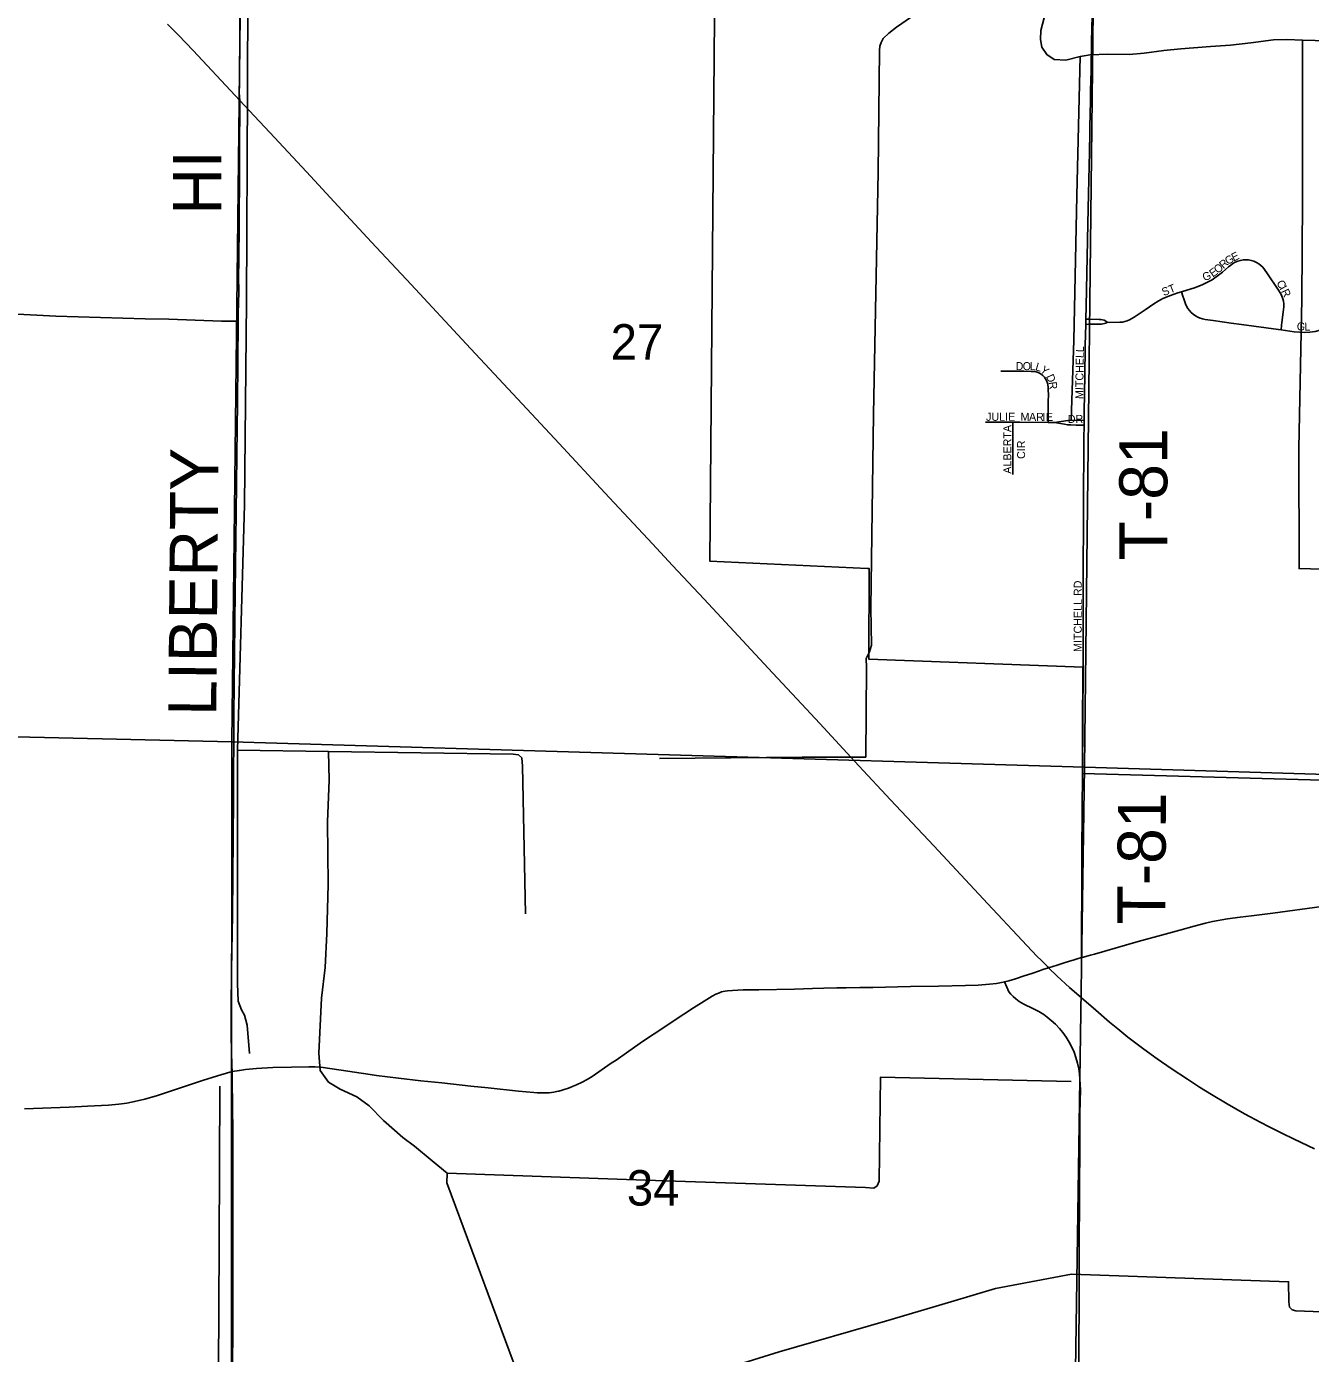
# Model space of a CAD drawing. Extents: x 1443599 to 1910620, y 1028088 to 1361369.
# Drawn here: x 1635252 to 1643273, y 1221564 to 1229853 of the extents above; entities that cross this region are included whole.
import ezdxf

# ---------------------------------------------------------------- set-up
doc = ezdxf.new("R2010")
doc.units = 0
for name, color, linetype in [('GM_X_City_Street', 7, 'Continuous'), ('GM_X_City_Street_Text', 7, 'Continuous'), ('GM_X_Corporation', 7, 'Continuous'), ('GM_X_County_Road', 7, 'Continuous'), ('GM_X_County_Road_Text', 7, 'Continuous'), ('GM_X_Minor_River', 7, 'Continuous'), ('GM_X_Section', 7, 'Continuous'), ('GM_X_Section_Text', 7, 'Continuous'), ('GM_X_Township_Road', 7, 'Continuous'), ('GM_X_Township_Road_Text', 7, 'Continuous'), ('GM_X_US_Route', 7, 'Continuous')]:
    doc.layers.add(name, color=color, linetype=linetype)

msp = doc.modelspace()

# ---------------------------------------------------------------- linework, layer by layer
at = {"layer": 'GM_X_City_Street'}
for points in [[(1641870.1, 1228025.2), (1641871.8, 1228106.3), (1641882.7, 1228621.4), (1641886.8, 1228808.4), (1641892.3, 1229070.9), (1641894.6, 1229188.5), (1641895.4, 1229228.4), (1641898, 1229385.9), (1641899.9, 1229468.9), (1641900.6, 1229500.7), (1641902.1, 1229592.6), (1641905.7, 1229746.8), (1641907.7, 1229848.5), (1641910.9, 1229973.2), (1641913.3, 1230078.2), (1641917.1, 1230219.2), (1641920.4, 1230383.3), (1641923.9, 1230505.5)], [(1642467.3, 1228196.1), (1642554.7, 1228223.6), (1642600.4, 1228241.5), (1642629.8, 1228255.6), (1642658.1, 1228271.8), (1642698.7, 1228299.2), (1642724.4, 1228319.5), (1642761.7, 1228351.9), (1642774.8, 1228362.4), (1642788.7, 1228372), (1642803.3, 1228380.5), (1642819, 1228387.2), (1642835.4, 1228392), (1642852.2, 1228395), (1642869.2, 1228395.9), (1642886.2, 1228395), (1642903.1, 1228392), (1642919.4, 1228387), (1642935, 1228380), (1642949.6, 1228371.3), (1642963.1, 1228360.9), (1642975.3, 1228349.1), (1642986.2, 1228336.2), (1643005.5, 1228308.9), (1643070.1, 1228213.1), (1643087.2, 1228184.4), (1643094.5, 1228169.1), (1643100.4, 1228153.2), (1643104.4, 1228136.7), (1643106.6, 1228120), (1643106.7, 1228103), (1643103.1, 1228069.6), (1643094.1, 1228004.4), (1643092.5, 1227988.1), (1643089.6, 1227958.7)], [(1642002.8, 1228005.9), (1642015.9, 1228005.4), (1642081.9, 1228006), (1642098, 1228007.1), (1642113.4, 1228009.9), (1642128.5, 1228014.7), (1642143.2, 1228021.2), (1642171.4, 1228037.2), (1642239.5, 1228083.3), (1642293.6, 1228121.3), (1642322, 1228138.6), (1642351.7, 1228153.7), (1642397.7, 1228172.8), (1642444.7, 1228188.9), (1642467.3, 1228196.1)], [(1642467.3, 1228196.1), (1642476.1, 1228168), (1642481, 1228152.2), (1642492.3, 1228121.2), (1642499.5, 1228106.4), (1642507.9, 1228092.3), (1642517.7, 1228079), (1642528.7, 1228066.7), (1642540.9, 1228055.7), (1642554.3, 1228046.1), (1642568.6, 1228038), (1642583.8, 1228031.6), (1642599.5, 1228026.6), (1642615.5, 1228022.9), (1642664.5, 1228016.1), (1642778.4, 1227999.3), (1642841.7, 1227991), (1643073, 1227961), (1643089.6, 1227958.7)], [(1643089.6, 1227958.7), (1643170.9, 1227947.1), (1643203.6, 1227943.4), (1643236.5, 1227942.6), (1643269.4, 1227944.6), (1643302.1, 1227949.1), (1643334.4, 1227955.7), (1643366.1, 1227964.8), (1643396.6, 1227977.1), (1643426.1, 1227991.8), (1643527.6, 1228046.9), (1643571.8, 1228068.9), (1643602.6, 1228080.8), (1643618.3, 1228085.5), (1643634.4, 1228089.2), (1643667.1, 1228093.9), (1643700, 1228095.6), (1643716.4, 1228095.1), (1643732.8, 1228093.3), (1643749.1, 1228090.6), (1643781, 1228082.3), (1643811.6, 1228070.1), (1643990, 1227984.7), (1644023.5, 1227968.6)], [(1641859.5, 1227392.6), (1641860.3, 1227460.5), (1641861.8, 1227546), (1641866.1, 1227831), (1641866.6, 1227863.5), (1641869.4, 1227992.8)], [(1641869.4, 1227992.8), (1641870.1, 1228025.2)], [(1641869.4, 1227992.8), (1641886.4, 1227993), (1641953.6, 1227993.3), (1641966.9, 1227994.5), (1641976.2, 1227996.1), (1641985.6, 1227997.3), (1641994.2, 1228000), (1642002.8, 1228005.9)], [(1641870.1, 1228025.2), (1641886.8, 1228025), (1641953.2, 1228023.8), (1641962.9, 1228023.2), (1641973.5, 1228021.5), (1641983.8, 1228018.5), (1641995, 1228012.9), (1642002.8, 1228005.9)], [(1641635.1, 1227380.4), (1641635.1, 1227408.7), (1641634.9, 1227510.8), (1641635.7, 1227553.5), (1641634.9, 1227583.1), (1641634.1, 1227601.4), (1641632, 1227615.8), (1641630, 1227625.5), (1641624.7, 1227641.1), (1641618.7, 1227652.9), (1641611.2, 1227663.6), (1641602, 1227673.1), (1641591.7, 1227681.2), (1641580.3, 1227687.9), (1641571.7, 1227692.2), (1641560.4, 1227695.7), (1641551.4, 1227697.3), (1641541.6, 1227698.4), (1641529.3, 1227699.1), (1641483.2, 1227699.8), (1641338.3, 1227699.6)], [(1641242.3, 1227382.8), (1641413.9, 1227381.7)], [(1641414.4, 1227054.8), (1641414.2, 1227173.6), (1641414.1, 1227264.7), (1641413.9, 1227354.9), (1641413.9, 1227381.7)], [(1641413.9, 1227381.7), (1641456.8, 1227381.5), (1641635.1, 1227380.4)], [(1641635.1, 1227380.4), (1641641.6, 1227380.3), (1641674.3, 1227379.8)], [(1641674.3, 1227379.8), (1641756.6, 1227392), (1641769.4, 1227393.1), (1641778, 1227393.4), (1641855.9, 1227392.6), (1641859.5, 1227392.6)], [(1641674.3, 1227379.8), (1641735.6, 1227369.4), (1641755.2, 1227366.2), (1641766.8, 1227364.8), (1641775.9, 1227364.3), (1641808.4, 1227363.4), (1641855.3, 1227363.2), (1641859.1, 1227363.2)], [(1641858, 1227275.4), (1641858.1, 1227279.6), (1641859.1, 1227363.2)], [(1641859.1, 1227363.2), (1641859.5, 1227392.6)], [(1641852.1, 1225851), (1641852.9, 1226241.7), (1641854.1, 1226486.9), (1641854, 1226512)]]:
    msp.add_lwpolyline(points, dxfattribs=at)
at = {"layer": 'GM_X_Corporation'}
msp.add_lwpolyline([(1644469.3, 1225113.5), (1641849.1, 1225187.9), (1641852.1, 1225851), (1640515.2, 1225901.2), (1640516.8, 1226466.9), (1640506.5, 1226467.4), (1639520.2, 1226514.5), (1639554.2, 1230393.3), (1639823.2, 1230383.9), (1639829.8, 1230585.9), (1640492.7, 1230559.9), (1640517.7, 1231451.5), (1639625.7, 1231464.8), (1639684.8, 1233228.6), (1640615.3, 1233192.7), (1640709.4, 1235840.8), (1642046.8, 1235796.5), (1642085.4, 1238455.5), (1644168.5, 1238399.6)], dxfattribs=at)
at = {"layer": 'GM_X_County_Road'}
for points in [[(1636583.8, 1229392.1), (1636581.2, 1229440.2), (1636582.7, 1229522), (1636584.2, 1229817.4), (1636585.1, 1230063.5), (1636586.9, 1230440.7), (1636586.5, 1230643.4)], [(1636574.6, 1228013.4), (1636575.1, 1228062.3), (1636578.6, 1228193.5), (1636577.3, 1228292), (1636578.4, 1228390.3), (1636579.8, 1228620), (1636581.6, 1228948.1), (1636582.8, 1229161.3), (1636584.9, 1229292.5), (1636585.6, 1229358.4), (1636583.8, 1229392.1)], [(1636536.5, 1223324.9), (1636535.4, 1223360.8), (1636532.7, 1223453), (1636531.2, 1223551.3), (1636530.8, 1223715.3), (1636532.7, 1223961.3), (1636538.1, 1224305.8), (1636542.6, 1224781.5), (1636544.3, 1225027.6), (1636547.1, 1225552.5), (1636555, 1226323.5), (1636561, 1226815.6), (1636566, 1227176.5), (1636570.1, 1227504.6), (1636574.6, 1228013.4)], [(1641841.9, 1224036.9), (1641847.7, 1224038.6), (1641898.1, 1224052.8), (1641923.4, 1224059.6), (1642117.6, 1224114.9), (1642196.4, 1224137.1), (1642364.8, 1224183.7), (1642457.4, 1224209.3), (1642547.3, 1224234.1), (1642617, 1224252.3), (1642662.1, 1224261.8), (1642755.2, 1224278.6), (1642833, 1224289.8), (1642904.6, 1224298.7), (1643038.2, 1224315.3), (1643343.9, 1224355.8)], [(1641636.7, 1223973.5), (1641691.4, 1223990.2), (1641741.6, 1224005.7), (1641781.7, 1224018.7)], [(1641781.7, 1224018.7), (1641791.4, 1224021.8), (1641816.3, 1224029.5), (1641841.9, 1224036.9)], [(1641361.6, 1223886.3), (1641388.8, 1223893), (1641429.8, 1223905.2), (1641484.6, 1223922.8)], [(1641484.6, 1223922.8), (1641533.1, 1223938.3), (1641580.8, 1223955.4)], [(1641580.8, 1223955.4), (1641601, 1223962.6), (1641636.7, 1223973.5)], [(1636536.5, 1223324.9), (1636582, 1223332.5), (1636619.6, 1223338.2), (1636688.9, 1223344.1), (1636791.6, 1223349.8), (1636908, 1223353.7), (1637016.1, 1223355.6), (1637055.3, 1223354.8), (1637091, 1223351.9), (1637162.4, 1223343), (1637399.3, 1223306.8), (1637438.3, 1223301.2), (1637575, 1223283.6), (1637715.4, 1223268.2), (1637845.9, 1223254.2), (1638028.7, 1223234.7), (1638136.5, 1223223.6), (1638325.7, 1223202.9), (1638420.5, 1223193.8), (1638442.6, 1223192.2), (1638460.1, 1223191.8), (1638486.6, 1223191.5), (1638516.4, 1223193.1), (1638532.1, 1223194.7), (1638546.1, 1223196.9), (1638563.2, 1223200.1), (1638578.5, 1223203.8), (1638598, 1223208.7), (1638616.8, 1223214.4), (1638632.7, 1223219.6), (1638648.1, 1223225.2), (1638667.9, 1223233.2), (1638687.8, 1223241.6), (1638723.5, 1223258.6), (1638755.5, 1223275.9), (1638786.4, 1223295), (1638905.4, 1223376.9), (1638934.9, 1223397.1), (1638999.4, 1223442), (1639051, 1223477), (1639107.5, 1223516.5), (1639172.7, 1223560.4), (1639359.2, 1223683), (1639418.7, 1223723.3), (1639536.3, 1223796.4), (1639559.3, 1223807.8), (1639580.9, 1223817.5), (1639594.4, 1223822.8), (1639605, 1223825.7), (1639617.5, 1223828.1), (1639630.5, 1223829.5), (1639663.3, 1223831.9), (1639728.7, 1223835), (1639827.7, 1223836.6), (1640049.7, 1223840.6), (1640162.7, 1223843.8), (1640232.3, 1223846), (1640314.1, 1223847.4), (1640373, 1223849.2), (1640458.2, 1223850.7), (1640540.1, 1223851), (1640773.6, 1223855.8), (1640949.7, 1223859), (1641118.7, 1223862.2), (1641196.6, 1223864.4), (1641268.8, 1223870.3), (1641311.3, 1223876.2), (1641352.5, 1223884.1), (1641361.6, 1223886.3)], [(1635239.3, 1223092.3), (1635518.1, 1223103.9), (1635632.8, 1223108.6), (1635764, 1223114.8), (1635829.6, 1223121), (1635878.6, 1223128), (1635927.1, 1223137.3), (1635991.1, 1223153.2), (1636070, 1223176.4), (1636194.9, 1223217.1), (1636350.5, 1223269.6), (1636444.2, 1223299.3), (1636523.1, 1223321.2), (1636536.5, 1223324.9)], [(1636480.1, 1220079.3), (1636494.3, 1220190.4), (1636513.6, 1220320.3), (1636525.4, 1220418.2), (1636532.4, 1220500.1), (1636535.8, 1220582.2), (1636536.5, 1220713.6), (1636536.8, 1220910.5), (1636537.7, 1221041.6), (1636539.1, 1221271.3), (1636538.3, 1221337.1), (1636536.6, 1221402.5), (1636538.5, 1221484.3), (1636540.4, 1221714.1), (1636540.2, 1221894.6), (1636540.9, 1222353.9), (1636540.3, 1222665.6), (1636540.7, 1222846), (1636540, 1222960.9), (1636539.4, 1223092.1), (1636537.6, 1223288.9), (1636536.5, 1223324.9)]]:
    msp.add_lwpolyline(points, dxfattribs=at)
at = {"layer": 'GM_X_Minor_River'}
for points in [[(1636644.4, 1223438), (1636630.9, 1223614.5), (1636613.1, 1223676.8), (1636595.2, 1223710.9), (1636575.3, 1223765.1), (1636569.6, 1223875.5), (1636570, 1225333.8), (1636614.6, 1226866.2), (1636626.5, 1228134), (1636632.4, 1229453.9), (1636634.3, 1230073.7), (1636638.2, 1230697.6), (1636641.5, 1231154.9), (1636640.3, 1231413.7), (1636520.1, 1231420.1), (1635959.2, 1231431.7), (1635494.5, 1231443.1)], [(1639206.2, 1225281.9), (1640097.7, 1225289.3), (1640494.4, 1225290.1), (1640500.1, 1225849.7), (1640498.2, 1225905.9), (1640518.4, 1225948), (1640530.5, 1225988.1), (1640527.2, 1226222.8), (1640542.9, 1227432.3), (1640573.5, 1228942.7), (1640581.8, 1229703), (1640583.8, 1229731), (1640591.9, 1229753.1), (1640604, 1229779.1), (1640638.2, 1229811.1), (1640686.4, 1229849.1), (1640780.7, 1229913), (1640913.1, 1229980.8), (1641019.5, 1230024.6), (1641119.7, 1230052.4), (1641260, 1230090), (1641430.4, 1230109.6), (1641548.6, 1230127.3), (1641642.8, 1230120.9)], [(1641610.1, 1229908.4), (1641587.8, 1229828.2), (1641585.6, 1229772.1), (1641595.5, 1229723.9), (1641625.4, 1229677.7), (1641671.4, 1229647.4), (1641745.5, 1229643.2), (1641833.7, 1229665), (1641897.9, 1229676.8), (1642008.1, 1229680.5), (1642140.3, 1229678.1), (1642234.5, 1229687.8), (1642356.7, 1229703.5), (1642462.9, 1229713.2), (1642649.3, 1229728.6), (1642773.5, 1229736.3), (1642899.7, 1229751.9), (1643042, 1229769.6), (1643126.2, 1229771.3), (1643224.3, 1229769), (1643540.8, 1229760)], [(1643224.3, 1229769), (1643223.3, 1228764), (1643219.5, 1228150.2), (1643200.6, 1227219.5), (1643202.4, 1226467.2), (1643272.5, 1226465), (1643546.9, 1226460.2), (1644175.9, 1226448.2), (1644716.8, 1226432.5), (1645209.6, 1226425)], [(1641833.7, 1229665), (1641813.1, 1228798.5), (1641794.3, 1227891.8), (1641778.8, 1227394.4)], [(1638369.9, 1224311.5), (1638350.6, 1225232.3), (1638346.8, 1225284.5), (1638324.8, 1225304.6), (1638292.8, 1225308.7), (1637138.9, 1225324.1), (1636570, 1225333.8)], [(1641778.4, 1223262.2), (1640586.5, 1223289.9), (1640578.5, 1222640), (1640566.4, 1222611.9), (1640544.4, 1222597.9), (1640494.3, 1222600.1), (1639118.1, 1222646.4), (1637880.2, 1222690.1), (1637786.3, 1222768.6), (1637676.4, 1222859.2), (1637602.4, 1222913.6), (1637482.6, 1223020.3), (1637392.7, 1223110.8), (1637314.7, 1223167.2), (1637210.7, 1223215.7), (1637138.7, 1223260), (1637086.8, 1223332.4), (1637079.1, 1223440.7), (1637094.2, 1223783.7), (1637118.8, 1223976.2), (1637127.5, 1224186.8), (1637136.4, 1224493.7), (1637131.6, 1224884.8), (1637142.4, 1225145.6), (1637138.9, 1225324.1)], [(1636459.5, 1223233.9), (1636456.5, 1222247), (1636449, 1221067.5), (1636447.1, 1220435.6), (1636422.6, 1220307.3), (1636396.1, 1220128.9), (1636363.4, 1219914.4), (1636344.8, 1219741.9), (1636328.2, 1219531.3), (1636301.5, 1219340.8), (1636299.8, 1218109.3)], [(1644484.4, 1221781.5), (1643182.4, 1221831.6), (1643158.4, 1221837.8), (1643142.4, 1221853.8), (1643138.5, 1221885.9), (1643136.9, 1222012.3), (1641780.8, 1222060.6), (1641305.7, 1221969.8), (1641027, 1221886.4), (1640618, 1221765.3), (1639954.3, 1221574.7), (1639132.2, 1221318.4), (1638347, 1221368.9), (1637878, 1222630), (1637880.2, 1222690.1)]]:
    msp.add_lwpolyline(points, dxfattribs=at)
at = {"layer": 'GM_X_Section'}
for points in [[(1631247.2, 1230796.7), (1636595.3, 1230648.8), (1636534.6, 1225385.5), (1631218.1, 1225507)], [(1636595.3, 1230648.8), (1640040.1, 1230599.8), (1641921.5, 1230497.2), (1641860.6, 1225227.8), (1636534.6, 1225385.5)], [(1641921.5, 1230497.2), (1644385, 1230387), (1647258, 1230369.4), (1647094.6, 1225069.2), (1641860.6, 1225227.8)], [(1636534.6, 1225385.5), (1636531.6, 1220105.4), (1636391.5, 1220105.2), (1631224.9, 1220206.8), (1631218.1, 1225507)], [(1641860.6, 1225227.8), (1641781.3, 1219928.7), (1636531.6, 1220105.4), (1636534.6, 1225385.5)], [(1641860.6, 1225227.8), (1647094.6, 1225069.2), (1647137.2, 1219766.5), (1641781.3, 1219928.7)]]:
    msp.add_lwpolyline(points, close=True, dxfattribs=at)
at = {"layer": 'GM_X_Township_Road'}
for points in [[(1635156.9, 1228058.4), (1635435.7, 1228044.6), (1635714.8, 1228036.6), (1635993.8, 1228027.8), (1636141.5, 1228024.7), (1636469.8, 1228013.6), (1636535.5, 1228012.8), (1636551.9, 1228013), (1636574.6, 1228013.4)], [(1641854, 1226512), (1641854, 1226512.6), (1641854, 1226512.6), (1641854.7, 1226709.4), (1641854.9, 1226837.1), (1641855, 1226964.9), (1641856.7, 1227170.4), (1641857, 1227213.9), (1641858, 1227275.4)], [(1641849.1, 1225187.9), (1641849.1, 1225189), (1641849.2, 1225303.8), (1641849.3, 1225353.2), (1641849.4, 1225486.2), (1641849.5, 1225559.9), (1641849.8, 1225585), (1641850.9, 1225714.6), (1641851.1, 1225740.2), (1641852, 1225847.9), (1641852.1, 1225851)], [(1641841.9, 1224036.9), (1641842, 1224063.5), (1641842.5, 1224237.3), (1641844.1, 1224421), (1641844.5, 1224575.2), (1641844.5, 1224686.8), (1641847.4, 1224962.3), (1641849.1, 1225187.9)], [(1641834.4, 1223142.1), (1641835.6, 1223210.4), (1641833.1, 1223277.9), (1641830.3, 1223310.6), (1641825.6, 1223343.1), (1641818.1, 1223378.4), (1641808.1, 1223413.1), (1641796, 1223447.1), (1641782.9, 1223477.2), (1641766.5, 1223509.4), (1641747.6, 1223540.2), (1641726.2, 1223569.3), (1641705.2, 1223594.5), (1641680.4, 1223620.8), (1641653.8, 1223645.2), (1641628.2, 1223665.7), (1641606.8, 1223680.9), (1641576.1, 1223699.8), (1641538.3, 1223719.6), (1641482.2, 1223747.1), (1641453.8, 1223763.7), (1641432.4, 1223778.9), (1641415, 1223793.8), (1641401.5, 1223808.1), (1641389.7, 1223823.9), (1641381.6, 1223838.1), (1641375.3, 1223853.3), (1641361.6, 1223886.3)], [(1641807.1, 1219917.5), (1641810.3, 1219961), (1641813.5, 1220034.7), (1641817.5, 1220116.7), (1641819.2, 1220198.7), (1641819.7, 1220447.2), (1641820.4, 1220838.9), (1641822.2, 1221157.3), (1641823.8, 1221354.3), (1641827.7, 1221876.2), (1641828.7, 1222152), (1641828.9, 1222289.8), (1641829.9, 1222483.5), (1641830.8, 1222648.1), (1641831.6, 1222798.5), (1641833, 1223061.3), (1641834.4, 1223142.1)]]:
    msp.add_lwpolyline(points, dxfattribs=at)
at = {"layer": 'GM_X_US_Route'}
for points in [[(1636132.8, 1229868.8), (1636202.3, 1229798.9), (1636292.7, 1229703.5), (1636583.8, 1229392.1), (1636642.4, 1229329.4), (1636773, 1229191.7), (1637001.2, 1228944.7), (1637198.4, 1228731.9), (1637406.7, 1228507.2), (1637655.3, 1228240.8), (1637999.3, 1227870.5), (1638348.5, 1227495.9), (1638579, 1227248.6), (1638865.6, 1226941.3), (1639162.7, 1226621.4), (1639287.5, 1226486.5), (1639484.9, 1226275.7), (1639885, 1225845.4), (1640093.7, 1225622.6), (1640208.2, 1225500.4), (1640452.4, 1225234.4), (1640649.8, 1225023.6), (1640919.4, 1224736.3), (1641256.6, 1224373.2), (1641472.1, 1224143.3), (1641564.7, 1224045.7), (1641591.9, 1224018.4)], [(1641591.9, 1224018.4), (1641629.4, 1223980.6), (1641636.7, 1223973.5), (1641690.9, 1223921.6), (1641768.6, 1223851.2), (1641932.2, 1223707.8), (1642018.6, 1223633.7), (1642070, 1223591.4), (1642133.1, 1223540.6), (1642232.2, 1223465.1), (1642314.5, 1223405.4), (1642403.5, 1223343.8), (1642504.8, 1223277), (1642580.3, 1223228), (1642654.7, 1223182.7), (1642753.1, 1223123.6), (1642861.4, 1223061.9), (1642962.4, 1223007.4), (1643011.2, 1222982.3), (1643093.7, 1222941.1), (1643170.5, 1222902.9), (1643298.2, 1222843)]]:
    msp.add_lwpolyline(points, dxfattribs=at)

# ---------------------------------------------------------------- texts
at = {"layer": 'GM_X_City_Street_Text'}
for s, rotation, p in [('R', 42.33312, (1642730.1, 1228337.1)), ('G', 32.09573, (1642757.5, 1228362.3)), ('E', 26.05186, (1642793.6, 1228385)), ('G', 21.15205, (1642609.7, 1228261.8)), ('E', 36.62168, (1642663.6, 1228284.7)), ('O', 39.29584, (1642693.9, 1228307.3)), ('ST', 21.80392, (1642356.2, 1228168.5)), ('C', 299.2056, (1643058.6, 1228252.5)), ('I', 299.24432, (1643077.9, 1228217.9)), ('R', 295.56569, (1643088.3, 1228199.5)), ('G', 355.0331, (1643185.7, 1227957.5)), ('L', 1.23779, (1643235.5, 1227953.6)), ('MITCHELL', 89.19436, (1641853.1, 1227525.9)), ('D', 359.75954, (1641431.2, 1227707.1)), ('O', 359.77873, (1641475.2, 1227707)), ('L', 359.7541, (1641519.2, 1227706.8)), ('L', 344.11465, (1641550.8, 1227707.1)), ('Y', 321.4426, (1641580.1, 1227699.9)), ('D', 295.57797, (1641619.5, 1227667.1)), ('R', 277.57379, (1641637.3, 1227631.4)), ('JULIE', 0.00001, (1641246.4, 1227390.3)), ('M', 359.79967, (1641462, 1227390.3)), ('A', 359.7814, (1641514.8, 1227390.2)), ('R', 359.80417, (1641558.8, 1227390)), ('I', 359.78148, (1641598.4, 1227389.9)), ('E', 359.79398, (1641620.4, 1227389.8)), ('DR', 0.00001, (1641756.9, 1227377.1)), ('ALBERTA', 90, (1641404.3, 1227059.7)), ('CIR', 90, (1641490.3, 1227152.1)), ('MITCHELL RD', 90, (1641844.2, 1225946.5))]:
    msp.add_text(s, height=50, rotation=rotation, dxfattribs=at).set_placement(p)
at = {"layer": 'GM_X_County_Road_Text'}
for s, rotation, p in [('HI', 90, (1636468.2, 1228678.9)), ('LIBERTY', 89.51231, (1636437.4, 1225546.5))]:
    msp.add_text(s, height=300, rotation=rotation, dxfattribs=at).set_placement(p)
at = {"layer": 'GM_X_Section_Text'}
for s, p in [('27', (1638901.3, 1227772.8)), ('34', (1639002.5, 1222488.5))]:
    msp.add_text(s, height=221, rotation=0.00001, dxfattribs=at).set_placement(p)
at = {"layer": 'GM_X_Township_Road_Text'}
for rotation, p in [(90, (1642378.7, 1226518.5)), (89.64834, (1642365.6, 1224243.2))]:
    msp.add_text('T-81', height=300, rotation=rotation, dxfattribs=at).set_placement(p)

doc.saveas('drawing.dxf')
